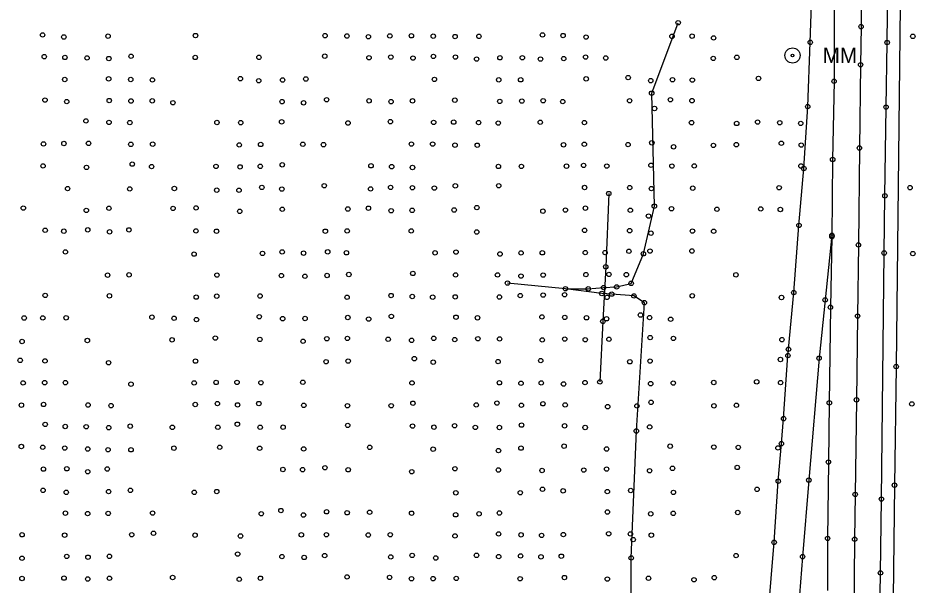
# Model space of a CAD drawing. Extents: x 20503438 to 20508873, y 7964251 to 7984667.
# Drawn here: x 20506272.5 to 20506679.9, y 7972207.3 to 7972464.8 of the extents above; entities that cross this region are included whole.
import ezdxf

# ---------------------------------------------------------------- set-up
doc = ezdxf.new("R2010")
doc.units = 0
for name, color, linetype in [('SurBreakLine', 7, 'Continuous'), ('SurConcreteSlab', 7, 'Continuous'), ('SurDrainageArrowDown', 7, 'Continuous'), ('SurDrainageArrowUp', 7, 'Continuous'), ('SurEdgeRoadPaved', 7, 'Continuous'), ('SurEdgeShoulderPaved', 7, 'Continuous'), ('SurFenceWire', 7, 'Continuous'), ('SurPointsNonDTM', 7, 'Continuous'), ('SurRoadPoints', 7, 'Continuous'), ('SurSurveyPoints', 7, 'Continuous')]:
    doc.layers.add(name, color=color, linetype=linetype)

msp = doc.modelspace()

# ---------------------------------------------------------------- linework, layer by layer
at = {"layer": 'SurBreakLine'}
msp.add_lwpolyline([(20506655.64, 7972480.95), (20506655.39, 7972460.82), (20506655.17, 7972443.54), (20506654.63, 7972405.71), (20506654.2, 7972361.71), (20506653.83, 7972329.4), (20506653.32, 7972291.37), (20506652.72, 7972248.45), (20506652.47, 7972228.07), (20506652.04, 7972192.65), (20506651.55, 7972160.21), (20506650.91, 7972116.84), (20506650.46, 7972080.66), (20506649.98, 7972043.26), (20506649.53, 7971999.86), (20506649.51, 7971997), (20506649.1, 7971970.31), (20506648.39, 7971913.22)], dxfattribs=at)
at = {"layer": 'SurConcreteSlab'}
msp.add_lwpolyline([(20506642.14, 7972366.07), (20506639.08, 7972336.72), (20506636.31, 7972310.27), (20506631.66, 7972254.92), (20506628.84, 7972220.16), (20506625.58, 7972179.88), (20506622.82, 7972145.41), (20506619.83, 7972106.64), (20506617.55, 7972077.44), (20506614.39, 7972037.44), (20506611.55, 7972002.25), (20506608.47, 7971964.14), (20506606.82, 7971943.7), (20506604.21, 7971911.77)], dxfattribs=at)
at = {"layer": 'SurDrainageArrowDown'}
msp.add_lwpolyline([(20506527.98, 7971858.82), (20506531.51, 7971910.07), (20506533.31, 7971971.31), (20506537.16, 7972033.43), (20506540.68, 7972099.35), (20506544.03, 7972158.32), (20506551.03, 7972173.45), (20506550.99, 7972219.57), (20506553.33, 7972277.23), (20506556.97, 7972335.48), (20506552.21, 7972338.55), (20506542.12, 7972339.37), (20506537.65, 7972339.65), (20506521.13, 7972341.81), (20506494.82, 7972344.4)], dxfattribs=at)
at = {"layer": 'SurDrainageArrowUp'}
msp.add_lwpolyline([(20506521.13, 7972341.81), (20506531.5, 7972341.78), (20506538.47, 7972342.35), (20506544.39, 7972342.64), (20506550.97, 7972344.26), (20506556.55, 7972357.69), (20506561.5, 7972379.29), (20506560.29, 7972430.59), (20506572.32, 7972462.6)], dxfattribs=at)
at = {"layer": 'SurEdgeRoadPaved'}
for points in [[(20506653.73, 7971380.9), (20506654.7, 7971481.23), (20506657.38, 7971669.1), (20506659.55, 7971851.97), (20506660.98, 7971956.86), (20506661.2, 7971992.92), (20506662.91, 7972124.86), (20506664.2, 7972212.79), (20506664.61, 7972246.33), (20506665.88, 7972358.05), (20506666.2, 7972384.01), (20506666.76, 7972424.32), (20506667.23, 7972453.6), (20506667.84, 7972505.25), (20506669.4, 7972614.97), (20506671.57, 7972775.78), (20506671.83, 7972814.97), (20506672.54, 7972877.32), (20506673.22, 7972920.01), (20506674.66, 7973031.32), (20506676.22, 7973136.41)], [(20506590.82, 7971915.24), (20506593.34, 7971949.22), (20506596.29, 7971982.15), (20506600.39, 7972034.16), (20506604.9, 7972087.86), (20506607.55, 7972123.27), (20506608.96, 7972142.44), (20506615.91, 7972226.68), (20506617.78, 7972254.42), (20506619.22, 7972271.47), (20506620.18, 7972282.83), (20506622.16, 7972311.47), (20506622.42, 7972314.33), (20506624.83, 7972340.08), (20506627.19, 7972370.59), (20506629.38, 7972396.4), (20506631.18, 7972424.53), (20506632.33, 7972453.69), (20506633.86, 7972497.27)], [(20506643.19, 7972470.31), (20506643.14, 7972436.02), (20506642.49, 7972400.52), (20506642.13, 7972365.44), (20506641.49, 7972333.42), (20506640.97, 7972290.02), (20506640.58, 7972263.1), (20506640.19, 7972228.47), (20506640.12, 7972204.86)]]:
    msp.add_lwpolyline(points, dxfattribs=at)
at = {"layer": 'SurEdgeShoulderPaved'}
msp.add_lwpolyline([(20506673.14, 7972470.38), (20506671.33, 7972306.45), (20506670.58, 7972252.62), (20506669.71, 7972176.11), (20506668.97, 7972139.22), (20506667.39, 7972020.06), (20506666.24, 7971916.08), (20506665.59, 7971878.76), (20506665.18, 7971833.22), (20506663.83, 7971727.76), (20506662.64, 7971620.3), (20506661.73, 7971558.42), (20506661.49, 7971544.36), (20506660.9, 7971513.48), (20506660.25, 7971439.17), (20506659.29, 7971365.69)], dxfattribs=at)
at = {"layer": 'SurFenceWire'}
msp.add_lwpolyline([(20506540.81, 7972385.04), (20506539.42, 7972351.78), (20506538.12, 7972327.02), (20506536.76, 7972299.5)], dxfattribs=at)
at = {"layer": 'SurPointsNonDTM'}
for centre in [(20506561.57, 7972423.66), (20506540.81, 7972385.04), (20506558.86, 7972374.82), (20506539.42, 7972351.78), (20506555.21, 7972329.88), (20506538.12, 7972327.02), (20506536.76, 7972299.5), (20506553.59, 7972288.61), (20506551.88, 7972227.93)]:
    msp.add_circle(centre, 1, dxfattribs=at)
at = {"layer": 'SurRoadPoints'}
for radius in [3.43, 0.571]:
    msp.add_circle((20506624.27, 7972447.74), radius, dxfattribs=at)
at = {"layer": 'SurSurveyPoints'}
for centre in [(20506572.32, 7972462.6), (20506655.39, 7972460.82), (20506283.67, 7972457.06), (20506293.31, 7972456.13), (20506313.42, 7972456.49), (20506353.11, 7972456.78), (20506411.97, 7972456.73), (20506421.89, 7972456.56), (20506431.63, 7972456.25), (20506441.36, 7972456.6), (20506451.17, 7972456.67), (20506461.08, 7972456.5), (20506471.01, 7972456.32), (20506481.81, 7972456.41), (20506510.71, 7972457.04), (20506520.04, 7972456.78), (20506530.51, 7972456.1), (20506569.51, 7972456.43), (20506578.66, 7972456.51), (20506588.43, 7972455.71), (20506632.33, 7972453.69), (20506667.23, 7972453.6), (20506678.89, 7972456.43), (20506284.4, 7972447.19), (20506293.81, 7972446.83), (20506303.85, 7972446.63), (20506313.74, 7972446.33), (20506323.84, 7972447.36), (20506353.02, 7972446.83), (20506381.93, 7972446.88), (20506411.83, 7972447.42), (20506431.91, 7972446.7), (20506441.83, 7972447), (20506451.9, 7972446.56), (20506461.16, 7972447.32), (20506471.17, 7972447.01), (20506480.79, 7972446.11), (20506491.39, 7972446.68), (20506501.55, 7972446.7), (20506509.8, 7972446.08), (20506520.35, 7972446.31), (20506530.28, 7972447), (20506539.43, 7972446.59), (20506588.25, 7972446.39), (20506598.96, 7972446.88), (20506655.17, 7972443.54), (20506373.52, 7972437.2), (20506549.62, 7972437.68), (20506608.8, 7972437.31), (20506293.74, 7972436.82), (20506313.67, 7972437.13), (20506323.7, 7972436.81), (20506333.53, 7972436.63), (20506381.84, 7972436.27), (20506392.67, 7972436.59), (20506403.21, 7972437.05), (20506461.64, 7972436.85), (20506490.82, 7972436.66), (20506500.8, 7972436.69), (20506530.53, 7972437.11), (20506559.89, 7972436.3), (20506569.74, 7972436.73), (20506578.75, 7972436.58), (20506643.14, 7972436.02), (20506560.29, 7972430.59), (20506284.77, 7972427.48), (20506294.64, 7972426.8), (20506313.92, 7972427.26), (20506323.82, 7972427.07), (20506333.46, 7972427.13), (20506342.84, 7972426.28), (20506392.45, 7972426.76), (20506402.22, 7972426.24), (20506412.66, 7972427.62), (20506431.95, 7972427.15), (20506441.95, 7972426.75), (20506451.68, 7972427.12), (20506470.89, 7972427.44), (20506491.31, 7972426.88), (20506501.32, 7972427.04), (20506511.02, 7972427.19), (20506519.91, 7972426.8), (20506550.25, 7972427.17), (20506568.8, 7972427.62), (20506578.61, 7972427.21), (20506631.18, 7972424.53), (20506666.76, 7972424.32), (20506303.36, 7972418), (20506313.82, 7972417.35), (20506323.29, 7972417.24), (20506362.83, 7972417.29), (20506373.65, 7972417.23), (20506392.24, 7972417.59), (20506422.38, 7972417.07), (20506441.62, 7972417.68), (20506461.27, 7972417.35), (20506470.37, 7972417.47), (20506481.68, 7972417.27), (20506490.62, 7972417.04), (20506509.69, 7972417.39), (20506529.73, 7972417.25), (20506578.39, 7972417.21), (20506598.9, 7972416.86), (20506608.4, 7972417.48), (20506618.47, 7972417.2), (20506628, 7972416.89), (20506284.07, 7972407.55), (20506293.33, 7972407.75), (20506304.53, 7972407.83), (20506323.75, 7972407.39), (20506333.66, 7972407.46), (20506372.98, 7972407.11), (20506382.71, 7972407.33), (20506401.86, 7972407.41), (20506411.24, 7972407.24), (20506451.17, 7972407.52), (20506460.82, 7972407.52), (20506470.98, 7972407), (20506481.07, 7972406.98), (20506520.26, 7972407.17), (20506529.7, 7972407.41), (20506549.57, 7972407.27), (20506560.35, 7972408.08), (20506570.24, 7972406.26), (20506588.34, 7972406.89), (20506598.75, 7972407.24), (20506619.18, 7972407.87), (20506628.21, 7972407.04), (20506654.63, 7972405.71), (20506642.49, 7972400.52), (20506283.88, 7972397.56), (20506303.61, 7972396.9), (20506324.38, 7972398.4), (20506333.17, 7972397.27), (20506362.41, 7972397.35), (20506373.34, 7972397.15), (20506382.52, 7972397.39), (20506392.5, 7972398.09), (20506432.81, 7972397.64), (20506442.2, 7972397.25), (20506451.65, 7972396.87), (20506490.69, 7972397.34), (20506501.13, 7972397.37), (20506521.61, 7972397.47), (20506529.39, 7972397.83), (20506539.91, 7972397.5), (20506559.99, 7972397.87), (20506569.47, 7972397.5), (20506579.65, 7972397.57), (20506628.12, 7972397.54), (20506629.38, 7972396.4), (20506411.57, 7972388.57), (20506471.11, 7972388.54), (20506490.82, 7972388.59), (20506295.03, 7972387.28), (20506323.24, 7972387.13), (20506343.51, 7972387.33), (20506362.76, 7972386.57), (20506372.88, 7972386.52), (20506383.23, 7972387.81), (20506392.33, 7972387.07), (20506432.64, 7972387.13), (20506441.72, 7972387.82), (20506451.62, 7972387.69), (20506461.59, 7972387.53), (20506529.84, 7972387.77), (20506550.32, 7972387.74), (20506560.15, 7972387.3), (20506578.93, 7972387.49), (20506618.18, 7972387.67), (20506677.65, 7972387.7), (20506666.2, 7972384.01), (20506274.91, 7972378.45), (20506303.53, 7972377.4), (20506313.78, 7972378.34), (20506342.93, 7972378.31), (20506353.36, 7972378.51), (20506373.19, 7972376.97), (20506392.51, 7972377.9), (20506422.29, 7972378.01), (20506431.66, 7972378.38), (20506441.97, 7972377.25), (20506451.51, 7972377.41), (20506470.58, 7972377.57), (20506480.88, 7972378.64), (20506510.88, 7972377.04), (20506521.09, 7972377.55), (20506530.18, 7972378.41), (20506550.59, 7972377.45), (20506561.5, 7972379.29), (20506569.3, 7972378.14), (20506589.91, 7972377.91), (20506609.82, 7972378.04), (20506618.73, 7972377.81), (20506284.83, 7972368.37), (20506293.32, 7972367.94), (20506304.15, 7972368.55), (20506322.88, 7972368.54), (20506353.29, 7972368.05), (20506362.66, 7972367.93), (20506412.08, 7972367.93), (20506421.99, 7972368.08), (20506451.08, 7972368.07), (20506529.83, 7972368.34), (20506550.29, 7972368.17), (20506578.82, 7972368.01), (20506588.44, 7972367.92), (20506627.19, 7972370.59), (20506314.08, 7972367.66), (20506480.85, 7972367.57), (20506559.97, 7972367.05), (20506642.13, 7972365.44), (20506642.14, 7972366.07), (20506654.2, 7972361.71), (20506294.04, 7972358.51), (20506352.46, 7972357.53), (20506383.55, 7972357.87), (20506392.48, 7972358.54), (20506402.18, 7972357.98), (20506413.14, 7972358.56), (20506421.67, 7972358.14), (20506461.91, 7972358.12), (20506471.41, 7972358.45), (20506491.4, 7972357.6), (20506500.97, 7972358.08), (20506510.62, 7972358.14), (20506530.14, 7972358.22), (20506539.11, 7972358.24), (20506549.94, 7972358.84), (20506556.55, 7972357.69), (20506559.52, 7972358.91), (20506578.57, 7972358.94), (20506665.88, 7972358.05), (20506678.91, 7972357.77), (20506313.18, 7972347.98), (20506322.93, 7972348.13), (20506362.83, 7972348.02), (20506392.13, 7972347.78), (20506412.87, 7972347.84), (20506422.74, 7972348.28), (20506451.83, 7972348.76), (20506471.23, 7972348.07), (20506490.28, 7972348.07), (20506500.95, 7972347.58), (20506511.02, 7972348.03), (20506530.41, 7972348.24), (20506540.88, 7972348.31), (20506548.78, 7972348.21), (20506598.53, 7972348.13), (20506402.81, 7972347.47), (20506494.82, 7972344.4), (20506550.97, 7972344.26), (20506521.13, 7972341.81), (20506531.5, 7972341.78), (20506537.65, 7972339.65), (20506538.47, 7972342.35), (20506542.12, 7972339.37), (20506544.39, 7972342.64), (20506624.83, 7972340.08), (20506284.85, 7972338.78), (20506314.03, 7972338.6), (20506353.43, 7972338.01), (20506362.74, 7972338.45), (20506382.45, 7972338.51), (20506421.97, 7972337.93), (20506441.95, 7972338.72), (20506451.57, 7972338.3), (20506460.83, 7972337.98), (20506471.1, 7972338.12), (20506491.12, 7972338.06), (20506500.61, 7972338.69), (20506511, 7972338.93), (20506520.74, 7972339.11), (20506540.05, 7972337.92), (20506552.21, 7972338.55), (20506556.97, 7972335.48), (20506578.73, 7972338.61), (20506619.25, 7972337.83), (20506639.08, 7972336.72), (20506641.49, 7972333.42), (20506275.3, 7972328.54), (20506283.76, 7972328.55), (20506294.36, 7972328.62), (20506333.34, 7972328.91), (20506343.4, 7972328.4), (20506353.55, 7972327.8), (20506382.06, 7972329.09), (20506392.71, 7972328.22), (20506402.86, 7972328.3), (20506422.28, 7972328.74), (20506431.76, 7972328.06), (20506442.06, 7972329.26), (20506471.42, 7972328.89), (20506481.18, 7972328.62), (20506510.45, 7972329.03), (20506520.83, 7972328.81), (20506530.7, 7972328.63), (20506539.79, 7972328.17), (20506559.35, 7972328.71), (20506568.91, 7972327.97), (20506653.83, 7972329.4), (20506362.11, 7972319.41), (20506412.75, 7972319.13), (20506422.11, 7972319.25), (20506461.3, 7972319.29), (20506481.35, 7972319.11), (20506491.22, 7972319.04), (20506559.61, 7972319.64), (20506570.17, 7972319.25), (20506274.34, 7972317.85), (20506303.99, 7972318.3), (20506342.46, 7972318.6), (20506382.33, 7972318.82), (20506401.95, 7972317.96), (20506440.61, 7972318.88), (20506451.25, 7972318.39), (20506470.83, 7972318.72), (20506510.61, 7972318.56), (20506520.79, 7972318.97), (20506530.11, 7972318.65), (20506540.86, 7972318.86), (20506619.44, 7972318.68), (20506622.16, 7972311.47), (20506622.42, 7972314.33), (20506273.47, 7972309.32), (20506284.77, 7972309.05), (20506313.62, 7972308.23), (20506353.1, 7972308.95), (20506412.43, 7972308.68), (20506422.44, 7972308.96), (20506452.5, 7972310.06), (20506461.07, 7972308.48), (20506490.55, 7972308.72), (20506509.91, 7972309.17), (20506550.36, 7972308.65), (20506559.55, 7972308.97), (20506618.78, 7972309.69), (20506636.31, 7972310.27), (20506671.33, 7972306.45), (20506274.83, 7972299.04), (20506284.6, 7972299.18), (20506294.03, 7972299.16), (20506352.51, 7972299.06), (20506362.48, 7972299.26), (20506371.96, 7972299.27), (20506382.83, 7972299.13), (20506401.85, 7972299.36), (20506451.43, 7972299.06), (20506491.12, 7972299.11), (20506500.93, 7972298.88), (20506510.12, 7972299.05), (20506530.02, 7972299.2), (20506559.84, 7972298.72), (20506570.11, 7972298.97), (20506588.5, 7972299.25), (20506607.98, 7972299.56), (20506618.82, 7972299.21), (20506323.82, 7972298.49), (20506520.26, 7972298.57), (20506653.32, 7972291.37), (20506274.07, 7972288.95), (20506284.13, 7972289.27), (20506304.32, 7972289.02), (20506314.78, 7972288.73), (20506353.01, 7972289.25), (20506363.05, 7972289.65), (20506372.24, 7972289.08), (20506381.87, 7972289.69), (20506402.3, 7972288.87), (20506422.13, 7972288.7), (20506441.99, 7972288.71), (20506451.85, 7972289.84), (20506480.62, 7972289.07), (20506490.01, 7972289.92), (20506501.12, 7972288.92), (20506510.92, 7972289.58), (20506521, 7972289.04), (20506540.31, 7972288.26), (20506560, 7972290.24), (20506588.56, 7972288.64), (20506598.79, 7972288.89), (20506640.97, 7972290.02), (20506678.44, 7972289.51), (20506620.18, 7972282.83), (20506284.85, 7972280.2), (20506293.96, 7972279.28), (20506303.47, 7972279.14), (20506313.71, 7972278.74), (20506323.46, 7972279.4), (20506342.59, 7972278.89), (20506363.26, 7972278.91), (20506372.12, 7972280.3), (20506382.48, 7972278.9), (20506392.91, 7972278.95), (20506422.24, 7972279.76), (20506451.68, 7972279.45), (20506461.39, 7972278.95), (20506470.77, 7972279.62), (20506480.19, 7972278.84), (20506491.12, 7972278.82), (20506501.18, 7972279.89), (20506520.76, 7972279.56), (20506530.09, 7972278.81), (20506559.38, 7972279.08), (20506553.33, 7972277.23), (20506274.02, 7972270.17), (20506520.53, 7972270.34), (20506568.69, 7972270.32), (20506619.22, 7972271.47), (20506283.73, 7972269.82), (20506293.71, 7972269.46), (20506304.16, 7972269.04), (20506313.41, 7972268.72), (20506323.83, 7972268.69), (20506343.29, 7972269.43), (20506364.11, 7972269.85), (20506382.25, 7972269.39), (20506402.23, 7972269.07), (20506432.25, 7972269.8), (20506461.04, 7972268.97), (20506490.71, 7972268.32), (20506500.93, 7972269.45), (20506539.81, 7972269.05), (20506588.51, 7972269.92), (20506599.62, 7972269.78), (20506617.67, 7972269.55), (20506640.58, 7972263.1), (20506284.03, 7972259.91), (20506294.66, 7972260.06), (20506304.17, 7972258.71), (20506313.02, 7972259.97), (20506392.8, 7972259.73), (20506401.75, 7972259.67), (20506411.88, 7972260.53), (20506422.46, 7972259.61), (20506451.34, 7972258.73), (20506470.95, 7972260.1), (20506490.7, 7972259.52), (20506510.52, 7972259.29), (20506529.46, 7972259.48), (20506539.8, 7972259.93), (20506559.32, 7972259.19), (20506569.74, 7972260.27), (20506599.14, 7972260.67), (20506617.78, 7972254.42), (20506631.66, 7972254.92), (20506283.9, 7972250.27), (20506323.53, 7972250.28), (20506362.76, 7972249.73), (20506510.71, 7972250.75), (20506520.08, 7972250.04), (20506550.77, 7972250.2), (20506608.17, 7972250.74), (20506670.58, 7972252.62), (20506294.4, 7972249.37), (20506313.66, 7972249.69), (20506352.56, 7972249.36), (20506471.33, 7972249.16), (20506500.59, 7972249.2), (20506540.15, 7972249.72), (20506570.18, 7972249.34), (20506652.72, 7972248.45), (20506664.61, 7972246.33), (20506294.04, 7972239.92), (20506304.13, 7972239.71), (20506313.46, 7972239.81), (20506333.63, 7972239.97), (20506382.97, 7972239.66), (20506391.91, 7972241.1), (20506402.15, 7972239.07), (20506412.64, 7972240.54), (20506421.98, 7972240.09), (20506432.21, 7972240.34), (20506451.24, 7972239.89), (20506471.27, 7972239.18), (20506481.89, 7972239.62), (20506491.13, 7972239.98), (20506540.18, 7972240.43), (20506559.86, 7972239.6), (20506570.07, 7972239.83), (20506599.38, 7972240.22), (20506274.36, 7972230.1), (20506293.69, 7972229.91), (20506324.15, 7972230.11), (20506334.04, 7972230.78), (20506352.9, 7972229.91), (20506373.55, 7972229.54), (20506401.19, 7972230.09), (20506412.56, 7972230.13), (20506431.59, 7972229.99), (20506441.58, 7972230.13), (20506470.97, 7972229.56), (20506490.77, 7972230.49), (20506500.98, 7972230.06), (20506510.3, 7972229.8), (20506520.17, 7972230.18), (20506540.77, 7972230.56), (20506550.65, 7972230.5), (20506560.13, 7972229.91), (20506615.91, 7972226.68), (20506640.19, 7972228.47), (20506652.47, 7972228.07), (20506372.26, 7972221.34), (20506274.31, 7972219.42), (20506294.63, 7972220.3), (20506304.29, 7972219.91), (20506314.03, 7972220.31), (20506392.37, 7972220.2), (20506402.46, 7972219.8), (20506411.78, 7972220.63), (20506441.8, 7972220.03), (20506451.52, 7972220.73), (20506462.24, 7972219.56), (20506480.73, 7972220.78), (20506490.8, 7972220.21), (20506500.74, 7972220.51), (20506510.03, 7972220.09), (20506519.25, 7972220.37), (20506550.99, 7972219.57), (20506598.61, 7972220.65), (20506628.84, 7972220.16), (20506274.32, 7972210.26), (20506293.38, 7972210.42), (20506304.18, 7972210.02), (20506314.04, 7972210.35), (20506342.73, 7972210.7), (20506372.96, 7972209.89), (20506382.57, 7972210.38), (20506421.94, 7972210.95), (20506441.24, 7972210.73), (20506451.22, 7972210.13), (20506461.04, 7972210.16), (20506471.54, 7972210.28), (20506500.55, 7972210.15), (20506520.68, 7972210.68), (20506540.16, 7972209.99), (20506558.84, 7972210.36), (20506579.52, 7972209.69), (20506588.7, 7972210.63), (20506664.2, 7972212.79)]:
    msp.add_circle(centre, 1, dxfattribs=at)

# ---------------------------------------------------------------- texts
at = {"layer": 'SurRoadPoints'}
msp.add_text('MM', height=6.995, rotation=360, dxfattribs=at).set_placement((20506637.98, 7972444.24))

doc.saveas('drawing.dxf')
